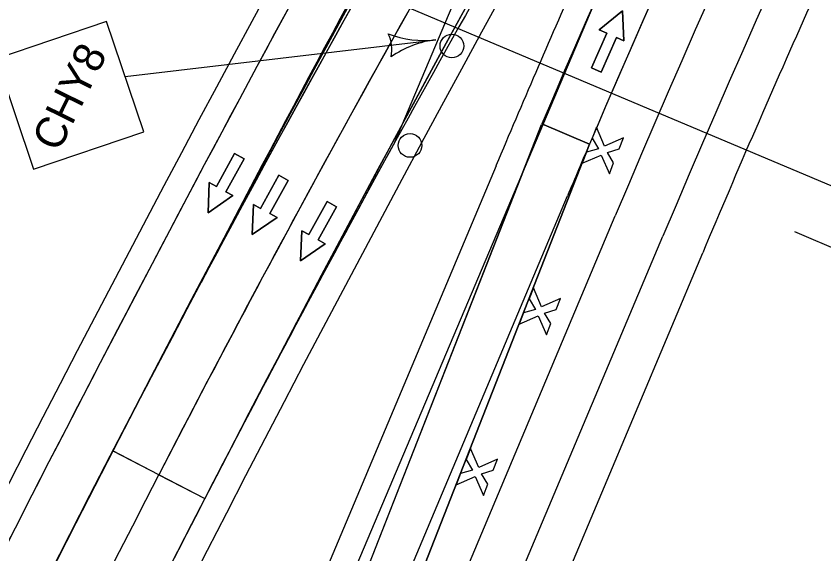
# Model space of a CAD drawing. Extents: x 14104283 to 14129344, y 8637090 to 8673339.
# Drawn here: x 14118812.8 to 14119000.1, y 8668379.3 to 8668503.9 of the extents above; entities that cross this region are included whole.
import ezdxf

# ---------------------------------------------------------------- set-up
doc = ezdxf.new("R2010")
doc.units = 0
for name, color, linetype in [('Cell', 7, 'Continuous'), ('dsnNonPlotable', 7, 'Continuous'), ('dsnPaintExistingBrokenLaneLineWhite', 7, 'Continuous'), ('dsnPaintExistingDottedLineWhite', 7, 'Continuous'), ('dsnPaintExistingEdgeLineLeftYellow', 7, 'Continuous'), ('dsnPaintExistingEdgeLineRightWhite', 7, 'Continuous'), ('dsnPaintExistingLaneLineWhite', 7, 'Continuous'), ('dsnPaintRemoveEdgeLineYellow', 7, 'Continuous'), ('dsnPaintRemoveLaneLineWhite', 7, 'Continuous'), ('dsnShadingPaved', 7, 'Continuous'), ('dsnStdLabel', 7, 'Continuous'), ('dsnStgShadingPrevPav', 7, 'Continuous'), ('dsnTapeExistingChannelizingLaneWhite', 7, 'Continuous'), ('dsnTapePlaceChannelizingLaneWhite', 7, 'Continuous'), ('dsnTapePlaceChannelizingLaneYellow', 7, 'Continuous'), ('Level 2', 7, 'Continuous'), ('Level 5', 7, 'Continuous')]:
    doc.layers.add(name, color=color, linetype=linetype)

msp = doc.modelspace()

# ---------------------------------------------------------------- linework, layer by layer
at = {"layer": 'Cell'}
for p, q in [((14118947.36, 8668478.15), (14118946.36, 8668475.59)), ((14118949.27, 8668473.78), (14118947.36, 8668478.15)), ((14118946.36, 8668475.59), (14118947.81, 8668473.14)), ((14118953.65, 8668475.69), (14118949.27, 8668473.78)), ((14118952.64, 8668473.13), (14118953.65, 8668475.69)), ((14118947.81, 8668473.14), (14118945.08, 8668472.34)), ((14118949.91, 8668472.32), (14118952.64, 8668473.13)), ((14118945.08, 8668472.34), (14118944.08, 8668469.78)), ((14118944.08, 8668469.78), (14118948.45, 8668471.69)), ((14118948.45, 8668471.69), (14118950.36, 8668467.31)), ((14118951.36, 8668469.87), (14118949.91, 8668472.32)), ((14118950.36, 8668467.31), (14118951.36, 8668469.87)), ((14118932.76, 8668440.91), (14118931.76, 8668438.35)), ((14118934.67, 8668436.54), (14118932.76, 8668440.91)), ((14118931.76, 8668438.35), (14118933.21, 8668435.9)), ((14118939.05, 8668438.45), (14118934.67, 8668436.54)), ((14118938.04, 8668435.89), (14118939.05, 8668438.45)), ((14118933.21, 8668435.9), (14118930.48, 8668435.1)), ((14118935.31, 8668435.08), (14118938.04, 8668435.89)), ((14118930.48, 8668435.1), (14118929.48, 8668432.54)), ((14118929.48, 8668432.54), (14118933.85, 8668434.45)), ((14118933.85, 8668434.45), (14118935.76, 8668430.07)), ((14118936.76, 8668432.63), (14118935.31, 8668435.08)), ((14118935.76, 8668430.07), (14118936.76, 8668432.63)), ((14118918.16, 8668403.67), (14118917.16, 8668401.11)), ((14118920.07, 8668399.3), (14118918.16, 8668403.67)), ((14118917.16, 8668401.11), (14118918.61, 8668398.66)), ((14118924.45, 8668401.21), (14118920.07, 8668399.3)), ((14118923.44, 8668398.65), (14118924.45, 8668401.21)), ((14118918.61, 8668398.66), (14118915.88, 8668397.86)), ((14118920.71, 8668397.84), (14118923.44, 8668398.65)), ((14118915.88, 8668397.86), (14118914.88, 8668395.29)), ((14118914.88, 8668395.29), (14118919.25, 8668397.21)), ((14118919.25, 8668397.21), (14118921.16, 8668392.83)), ((14118922.16, 8668395.39), (14118920.71, 8668397.84)), ((14118921.16, 8668392.83), (14118922.16, 8668395.39))]:
    msp.add_line(p, q, dxfattribs=at)
for centre in [(14118913.86, 8668496.97), (14118904.15, 8668473.93)]:
    msp.add_circle(centre, 2.75, dxfattribs=at)
at = {"layer": 'dsnNonPlotable'}
msp.add_lwpolyline([(14118056.48, 8667161.91), (14118665.06, 8668606.45), (14119130.44, 8668410.38), (14118521.87, 8666965.84)], close=True, dxfattribs=at)
at = {"layer": 'dsnPaintExistingBrokenLaneLineWhite'}
msp.add_line((14118863.73, 8668248.6), (14118951.74, 8668457.58), dxfattribs=at)
for centre, radius, start, end in [((14121592.11, 8667345.68), 2864.95, 147.15737, 157.1633), ((14121955.85, 8666791.92), 3500, 149.50762, 152.69211), ((14123732.96, 8665874.38), 5500, 152.69211, 157.1633)]:
    msp.add_arc(centre, radius, start, end, dxfattribs=at)
at = {"layer": 'dsnPaintExistingDottedLineWhite'}
msp.add_arc((14123732.96, 8665874.38), 5512, 152.23375, 154.51073, dxfattribs=at)
at = {"layer": 'dsnPaintExistingEdgeLineLeftYellow'}
for centre, radius, start, end in [((14121955.85, 8666791.92), 3488, 149.50762, 152.69211), ((14123732.96, 8665874.38), 5488, 152.69211, 157.1633)]:
    msp.add_arc(centre, radius, start, end, dxfattribs=at)
at = {"layer": 'dsnPaintExistingEdgeLineRightWhite'}
msp.add_line((14118874.68, 8668243.67), (14118962.79, 8668452.92), dxfattribs=at)
for centre, radius, start, end in [((14121592.11, 8667345.68), 2852.95, 147.15737, 157.1633), ((14123732.96, 8665874.38), 5524, 150.3689, 156.09858)]:
    msp.add_arc(centre, radius, start, end, dxfattribs=at)
at = {"layer": 'dsnPaintExistingLaneLineWhite'}
msp.add_arc((14122745.39, 8666422.79), 4382.73, 149.34837, 152.56312, dxfattribs=at)
at = {"layer": 'dsnPaintRemoveEdgeLineYellow'}
msp.add_line((14118852.57, 8668283.93), (14118948.15, 8668509.94), dxfattribs=at)
at = {"layer": 'dsnPaintRemoveLaneLineWhite'}
msp.add_line((14118863.63, 8668279.27), (14118940.68, 8668462.24), dxfattribs=at)
for start, end in [(153.70867, 156.90337), (156.90337, 157.1633)]:
    msp.add_arc((14121592.11, 8667345.68), 2876.95, start, end, dxfattribs=at)
at = {"layer": 'dsnShadingPaved'}
for p, q in [((14118900.6, 8668474.65), (14118939.91, 8668567.91)), ((14118759.32, 8668031.57), (14118934.6, 8668478.63)), ((14118934.73, 8668478.96), (14118945.77, 8668474.25)), ((14118945.77, 8668474.25), (14118934.73, 8668478.96)), ((14118945.77, 8668474.25), (14118770.49, 8668027.18)), ((14118845.91, 8668397.62), (14118835.25, 8668403.13)), ((14118835.25, 8668403.13), (14118856.57, 8668392.12)), ((14118845.91, 8668397.62), (14118856.57, 8668392.12))]:
    msp.add_line(p, q, dxfattribs=at)
for centre, radius, start, end in [((14121955.85, 8666791.92), 3512, 144.95493, 152.69211), ((14121955.85, 8666791.92), 3500, 144.95493, 152.69211), ((14121592.11, 8667345.68), 2888.95, 151.24538, 156.90337), ((14121592.11, 8667345.68), 2876.95, 151.24538, 156.90337), ((14123732.96, 8665874.38), 5512, 149.67774, 156.09858), ((14123732.96, 8665874.38), 5524, 150.3689, 153.23374), ((14121955.85, 8666791.92), 3500, 149.50762, 152.69211), ((14121955.85, 8666791.92), 3488, 151.15555, 152.69211), ((14123732.96, 8665874.38), 5512, 152.69211, 153.16925), ((14123732.96, 8665874.38), 5488, 152.69211, 157.1633)]:
    msp.add_arc(centre, radius, start, end, dxfattribs=at)
at = {"layer": 'dsnStdLabel'}
for p, q in [((14118838.09, 8668489.89), (14118910.16, 8668498.4)), ((14118993.28, 8668453.99), (14119052.46, 8668428.75))]:
    msp.add_line(p, q, dxfattribs=at)
msp.add_lwpolyline([(14118816.84, 8668468.45), (14118842.41, 8668477.1), (14118833.76, 8668502.68), (14118808.18, 8668494.02)], close=True, dxfattribs=at)
for centre, radius, start, end in [((14118907.46, 8668521.19), 22.95, 248.6667, 276.738), ((14118891.05, 8668496.15), 8.86, 349.0037, 24.4721), ((14118912.85, 8668475.61), 22.95, 96.7379, 124.8091)]:
    msp.add_arc(centre, radius, start, end, dxfattribs=at)
at = {"layer": 'dsnStgShadingPrevPav'}
for p, q in [((14118924.09, 8668469.22), (14118847.04, 8668286.26)), ((14118848.39, 8668155.49), (14118972.01, 8668449.04))]:
    msp.add_line(p, q, dxfattribs=at)
for centre, radius, start, end in [((14123732.96, 8665874.38), 5512, 146.42562, 157.1633), ((14123732.96, 8665874.38), 5488, 146.42119, 157.1633), ((14123732.96, 8665874.38), 5530, 150.3689, 156.09911), ((14123732.96, 8665874.38), 5524, 150.3689, 156.09858), ((14123732.96, 8665874.38), 5524, 150.3689, 156.09858), ((14123732.59, 8665873.82), 5512, 150.36196, 157.1633), ((14123732.96, 8665874.38), 5482, 150.67101, 157.1633), ((14123732.96, 8665874.38), 5488, 151.14296, 157.1633), ((14121592.11, 8667345.68), 2894.95, 156.23384, 157.1633), ((14121592.11, 8667345.68), 2842.95, 155.90343, 157.1633)]:
    msp.add_arc(centre, radius, start, end, dxfattribs=at)
at = {"layer": 'dsnTapeExistingChannelizingLaneWhite'}
msp.add_arc((14121955.85, 8666791.92), 3512, 147.96378, 151.97273, dxfattribs=at)
at = {"layer": 'dsnTapePlaceChannelizingLaneWhite'}
msp.add_line((14118770.49, 8668027.18), (14118945.77, 8668474.25), dxfattribs=at)
msp.add_arc((14121592.11, 8667345.68), 2876.95, 151.24538, 156.90337, dxfattribs=at)
at = {"layer": 'dsnTapePlaceChannelizingLaneYellow'}
for p, q in [((14118900.6, 8668474.65), (14118939.91, 8668567.91)), ((14118759.32, 8668031.57), (14118934.66, 8668478.8))]:
    msp.add_line(p, q, dxfattribs=at)
msp.add_arc((14121592.11, 8667345.68), 2888.95, 151.24538, 156.90337, dxfattribs=at)
at = {"layer": 'Level 2'}
for points in [[(14118946.21, 8668491.93), (14118948.5, 8668490.92), (14118952.04, 8668498.93), (14118953.75, 8668498.17), (14118953.42, 8668505.15), (14118948.04, 8668500.7), (14118949.75, 8668499.94)], [(14118865.67, 8668470.86), (14118863.48, 8668472.06), (14118859.26, 8668464.4), (14118857.61, 8668465.3), (14118857.34, 8668458.32), (14118863.09, 8668462.29), (14118861.45, 8668463.19)], [(14118875.9, 8668465.8), (14118873.71, 8668467), (14118869.49, 8668459.34), (14118867.85, 8668460.24), (14118867.57, 8668453.26), (14118873.33, 8668457.23), (14118871.68, 8668458.13)], [(14118887.09, 8668459.71), (14118884.9, 8668460.92), (14118880.67, 8668453.25), (14118879.03, 8668454.16), (14118878.76, 8668447.18), (14118884.51, 8668451.14), (14118882.86, 8668452.05)]]:
    msp.add_lwpolyline(points, close=True, dxfattribs=at)
at = {"layer": 'Level 5'}
for points in [[(14118949.75, 8668499.94), (14118948.04, 8668500.7), (14118953.42, 8668505.15), (14118953.75, 8668498.17), (14118952.04, 8668498.93), (14118948.5, 8668490.92), (14118946.21, 8668491.93), (14118949.75, 8668499.94)], [(14118861.45, 8668463.19), (14118863.09, 8668462.29), (14118857.34, 8668458.32), (14118857.61, 8668465.3), (14118859.26, 8668464.4), (14118863.48, 8668472.06), (14118865.67, 8668470.86), (14118861.45, 8668463.19)], [(14118871.68, 8668458.13), (14118873.33, 8668457.23), (14118867.57, 8668453.26), (14118867.85, 8668460.24), (14118869.49, 8668459.34), (14118873.71, 8668467), (14118875.9, 8668465.8), (14118871.68, 8668458.13)], [(14118882.86, 8668452.05), (14118884.51, 8668451.14), (14118878.76, 8668447.18), (14118879.03, 8668454.16), (14118880.67, 8668453.25), (14118884.9, 8668460.92), (14118887.09, 8668459.71), (14118882.86, 8668452.05)]]:
    msp.add_lwpolyline(points, dxfattribs=at)

# ---------------------------------------------------------------- texts
at = {"layer": 'dsnStdLabel'}
msp.add_text('CHY8', height=7.2, rotation=63.6912, dxfattribs=at).set_placement((14118822.68, 8668472.14))

doc.saveas('drawing.dxf')
